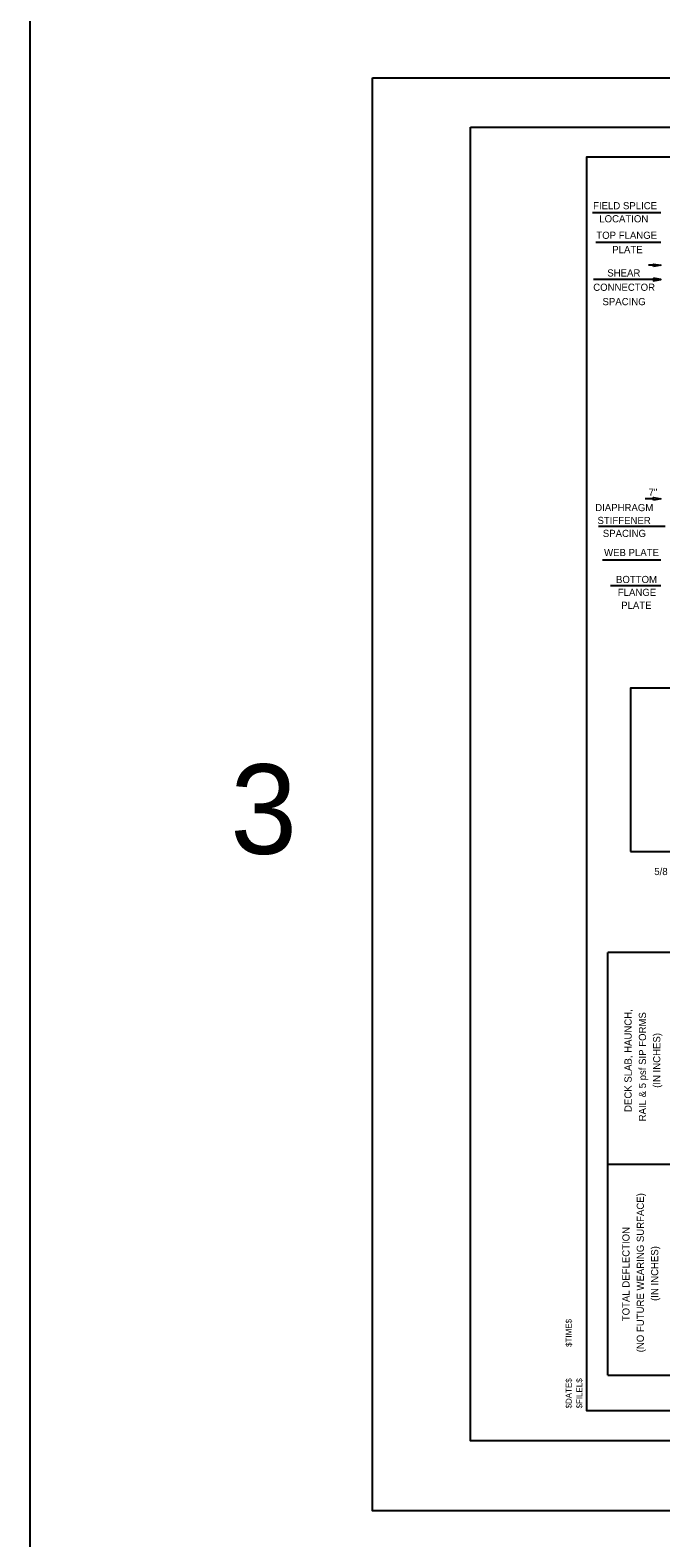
# Model space of a CAD drawing. Extents: x 4944 to 17449, y 3824 to 49087.
# Drawn here: x 10071 to 11084, y 5720 to 8144 of the extents above; entities that cross this region are included whole.
import ezdxf

# ---------------------------------------------------------------- set-up
doc = ezdxf.new("R2010")
doc.units = 0
for name, color, linetype in [('36_S_LINES', 7, 'Continuous'), ('37_S_TXT', 7, 'Continuous'), ('3A', 7, 'Continuous'), ('DIM', 7, 'Continuous'), ('HATCH', 7, 'Continuous'), ('Level 14', 7, 'Continuous'), ('Level 34', 7, 'Continuous'), ('steel', 7, 'Continuous')]:
    doc.layers.add(name, color=color, linetype=linetype)

# ---------------------------------------------------------------- blocks, each defined once
blk = doc.blocks.new('STAMP_')
at = {"layer": 'steel'}
for s, p in [('$TIME$', (8.01, 7.43)), ('$DATE$', (8.01, 2.56)), ('$FILEL$', (8.85, 2.56))]:
    blk.add_text(s, height=0.472, rotation=90, dxfattribs=at).set_placement(p)

msp = doc.modelspace()

# ---------------------------------------------------------------- linework, layer by layer
at = {"layer": '36_S_LINES'}
for p, q in [((10974.6, 7850.7), (11084.3, 7850.7)), ((10979.9, 7803.1), (11084.3, 7803.1)), ((11072.3, 7765.9), (11064.6, 7765.9)), ((11077.8, 7743), (10976.2, 7743)), ((11072.3, 7390.4), (11059.3, 7390.4)), ((11091.3, 7345.8), (10984.1, 7345.8)), ((10990.7, 7292.3), (11084.3, 7292.3)), ((11003.2, 7251.1), (11084.4, 7251.1))]:
    msp.add_line(p, q, dxfattribs=at)
for points in [[(11072.3, 7763.9), (11072.3, 7767.9), (11084.3, 7765.9)], [(11072.3, 7745), (11072.3, 7741), (11084.3, 7743)], [(11072.3, 7388.4), (11072.3, 7392.4), (11084.3, 7390.4)]]:
    msp.add_lwpolyline(points, close=True, dxfattribs=at)
at = {"layer": '37_S_TXT'}
msp.add_lwpolyline([(10621.1, 8067.3), (14077.1, 8067.3), (14077.1, 5763.3), (10621.1, 5763.3)], close=True, dxfattribs=at)
at = {"layer": 'DEFPOINTS'}
msp.add_lwpolyline([(11035.6, 6823.4), (13662, 6823.4), (13662, 7085.9), (11035.6, 7085.9)], close=True, dxfattribs=at)
at = {"layer": 'DIM'}
msp.add_lwpolyline([(10778.3, 7988.1), (14042.3, 7988.1), (14042.3, 5876.1), (10778.3, 5876.1)], close=True, dxfattribs=at)
at = {"layer": 'HATCH'}
msp.add_line((10071.2, 4923.7), (10071.2, 11489.8), dxfattribs=at)
at = {"layer": 'Level 14'}
msp.add_lwpolyline([(13989.5, 5924.1), (10965.5, 5924.1), (10965.5, 7940.1), (13989.5, 7940.1)], close=True, dxfattribs=at)
at = {"layer": 'Level 34'}
for p, q in [((10999.3, 5981.6), (10999.3, 6660.9)), ((12201.6, 6660.9), (10999.3, 6660.9)), ((10999.3, 6321), (12201.6, 6321)), ((10999.3, 5981.6), (12201.6, 5981.6))]:
    msp.add_line(p, q, dxfattribs=at)

# ---------------------------------------------------------------- block references
at = {"layer": 'steel', "xscale": 20.320040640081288, "yscale": 20.320040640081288}
msp.add_blockref('STAMP_', (10778.3, 5876.1), dxfattribs=at)

# ---------------------------------------------------------------- texts
at = {"layer": '3A'}
for s, p in [('FIELD SPLICE', (10975.5, 7856)), ('LOCATION', (10985.4, 7835)), ('TOP FLANGE ', (10980.7, 7808.5)), ('PLATE', (11006.3, 7785.4)), ('SHEAR ', (10998.3, 7747.9)), ('CONNECTOR', (10975.7, 7724.9)), ('SPACING', (10990.6, 7701.8)), ('7"', (11064.6, 7395.4)), ('DIAPHRAGM ', (10978.9, 7370.7)), ('STIFFENER ', (10982.5, 7350)), ('SPACING', (10991.1, 7329.2)), ('WEB PLATE', (10993.1, 7298.4)), ('BOTTOM ', (11012.3, 7255.1)), ('FLANGE', (11015.2, 7234.4)), ('PLATE', (11020.6, 7213.6)), ('5/8 BEARING ', (11073.8, 6785.6))]:
    msp.add_text(s, height=11.52, dxfattribs=at).set_placement(p)
for s, p in [('DECK SLAB, HAUNCH,', (11037.4, 6404.8)), ('RAIL & 5 psf SIP FORMS', (11060.5, 6389.7)), ('(IN INCHES)', (11083.5, 6443.6)), ('(NO FUTURE WEARING SURFACE)', (11057.1, 6018.4)), ('TOTAL DEFLECTION', (11034, 6068.4)), ('(IN INCHES)', (11080.1, 6101))]:
    msp.add_text(s, height=11.52, rotation=90, dxfattribs=at).set_placement(p)
at = {"layer": 'HATCH'}
msp.add_text('3', height=144, dxfattribs=at).set_placement((10392.7, 6819.7))

doc.saveas('drawing.dxf')
